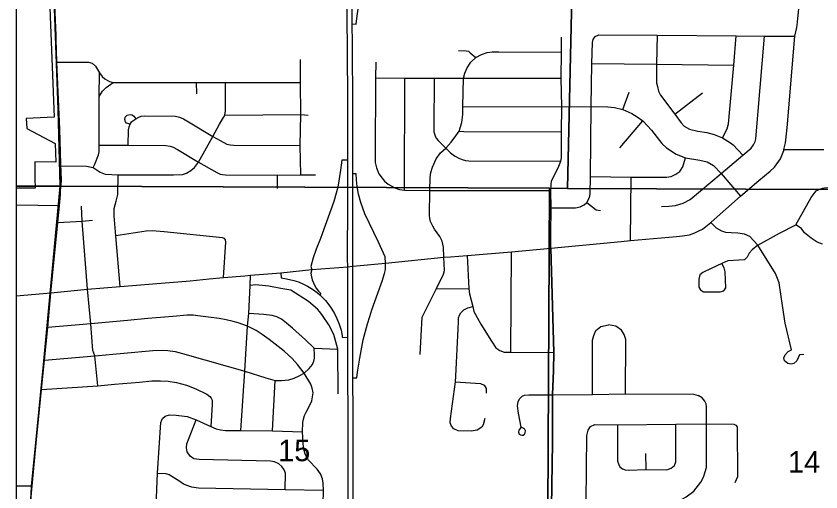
# Model space of a CAD drawing. Extents: x -38.1 to 35.9, y -2.7 to 28.5.
# Drawn here: x 8.115 to 9.678, y 15.282 to 16.206 of the extents above; entities that cross this region are included whole.
import ezdxf

# ---------------------------------------------------------------- set-up
doc = ezdxf.new("R2010")
doc.units = 0
for name, color, linetype in [('GM_X_City_Street', 7, 'Continuous'), ('GM_X_City_Street_Text', 7, 'Continuous'), ('GM_X_Corporation', 7, 'Continuous'), ('GM_X_Corporation_Text', 7, 'Continuous'), ('GM_X_Major_River', 7, 'Continuous'), ('GM_X_Minor_River', 7, 'Continuous'), ('GM_X_Rail_Line_Text', 7, 'Continuous'), ('GM_X_US_Route', 7, 'Continuous')]:
    doc.layers.add(name, color=color, linetype=linetype)

msp = doc.modelspace()

# ---------------------------------------------------------------- linework, layer by layer
at = {"layer": 'GM_X_City_Street'}
for p, q in [((8.8687, 15.8678), (8.8694, 16.0858)), ((8.4654, 16.055), (8.4653, 16.077)), ((9.2932, 16.0244), (9.3049, 16.0583)), ((9.3937, 16.0157), (9.4475, 16.0568)), ((9.2869, 15.9502), (9.3317, 16.0024)), ((9.6058, 15.947), (9.6831, 15.9473)), ((8.6221, 15.8716), (8.6225, 15.897)), ((9.3075, 15.7701), (9.3088, 15.8935)), ((8.1146, 15.8394), (8.1991, 15.8385)), ((9.153, 15.7552), (9.1532, 15.7832)), ((9.153, 15.7552), (9.2899, 15.7684)), ((9.0756, 15.5533), (9.0768, 15.7482)), ((8.9311, 15.6771), (8.9937, 15.6767)), ((8.6936, 15.5616), (8.7394, 15.5592)), ((8.2731, 15.4881), (8.2681, 15.5401)), ((8.6127, 15.4007), (8.618, 15.4988)), ((9.3383, 15.3258), (9.3378, 15.3567)), ((8.1146, 15.2942), (8.1449, 15.2942))]:
    msp.add_line(p, q, dxfattribs=at)
for points in [[(9.6318, 16.194), (9.6477, 16.3507), (9.6404, 16.3717), (9.6476, 16.4723), (9.6557, 16.5731), (9.6614, 16.6273), (9.6602, 16.6447), (9.6546, 16.6676), (9.6322, 16.744), (9.6013, 16.8489), (9.5885, 16.8705), (9.5494, 16.9278), (9.5194, 16.9778), (9.4899, 17.0395), (9.4492, 17.1302), (9.4087, 17.2248), (9.3808, 17.2922), (9.3578, 17.3731), (9.3429, 17.4462)], [(9.5876, 15.9128), (9.5988, 15.9287), (9.6054, 15.9452), (9.6058, 15.947), (9.6089, 15.9597), (9.6121, 15.9891), (9.6172, 16.0506), (9.6232, 16.1212), (9.6272, 16.1669), (9.6308, 16.1841), (9.6318, 16.194)], [(9.1532, 15.7832), (9.1536, 15.8337), (9.1531, 15.8674), (9.1536, 15.8794), (9.1547, 15.8857), (9.1606, 15.899), (9.1673, 15.9117), (9.1723, 15.9242), (9.1736, 15.9311), (9.1738, 15.9812), (9.1742, 16.0297), (9.1734, 16.0855), (9.1741, 16.1361), (9.1739, 16.1653)], [(9.1536, 15.8337), (9.2013, 15.8335), (9.2101, 15.8358), (9.2176, 15.8397), (9.2229, 15.8443), (9.2282, 15.8542), (9.2295, 15.8606), (9.2302, 15.8945), (9.2312, 16.0303), (9.2325, 16.1143), (9.2338, 16.1547), (9.2352, 16.1603), (9.2393, 16.1663), (9.2462, 16.1699), (9.3598, 16.1691), (9.5133, 16.1679), (9.5683, 16.1673), (9.6272, 16.1669)], [(9.3598, 16.1691), (9.3585, 16.1128), (9.3585, 16.0764), (9.3601, 16.0693), (9.3624, 16.0602), (9.3659, 16.0527), (9.3937, 16.0157), (9.4063, 15.9989), (9.4122, 15.9924), (9.4227, 15.9863), (9.4384, 15.9829), (9.456, 15.9801), (9.4702, 15.9764), (9.4863, 15.9698), (9.5023, 15.9597), (9.5075, 15.9559), (9.5258, 15.9362)], [(9.3679, 15.8364), (9.3823, 15.8369), (9.3953, 15.8382), (9.4103, 15.8426), (9.4239, 15.85), (9.4842, 15.9002), (9.5258, 15.9362), (9.5424, 15.9499), (9.5468, 15.956), (9.5496, 15.9626), (9.551, 15.968), (9.5683, 16.1673)], [(9.4863, 15.9698), (9.4957, 15.987), (9.4984, 15.9972), (9.5086, 16.1111), (9.5133, 16.1679)], [(8.8993, 15.5493), (8.9033, 15.6217), (8.9068, 15.6296), (8.9311, 15.6771), (8.9447, 15.705), (8.9468, 15.7123), (8.9456, 15.7378), (8.9445, 15.7577), (8.942, 15.769), (8.9375, 15.7781), (8.9275, 15.7921), (8.9238, 15.798), (8.9195, 15.8073), (8.9182, 15.8133), (8.9176, 15.8194), (8.9183, 15.8677), (8.919, 15.8929), (8.9201, 15.9026), (8.9233, 15.9127), (8.9306, 15.9291), (8.9391, 15.9403), (8.9494, 15.9498), (8.9598, 15.961), (8.9688, 15.9736), (8.9752, 15.9829), (8.9804, 15.9997), (8.9823, 16.0147), (8.9822, 16.0303), (8.9836, 16.0854), (8.9861, 16.0951), (8.9905, 16.1054), (8.9979, 16.1163), (9.0073, 16.1257), (9.0184, 16.1316), (9.0292, 16.1351), (9.039, 16.1367), (9.052, 16.1366), (9.1741, 16.1361)], [(8.9735, 16.139), (8.9884, 16.1386), (8.993, 16.1377), (8.9967, 16.135), (9.0073, 16.1257)], [(8.1939, 16.1168), (8.2469, 16.1168), (8.2552, 16.1165), (8.2622, 16.1144), (8.2691, 16.1091), (8.2765, 16.0958), (8.2819, 16.0889), (8.2872, 16.084), (8.296, 16.0793), (8.3032, 16.077), (8.3141, 16.077), (8.4653, 16.077), (8.5215, 16.077), (8.6672, 16.0773)], [(8.6673, 15.8982), (8.6665, 15.9547), (8.6673, 16.0153), (8.6672, 16.0773), (8.6671, 16.1219)], [(8.813, 16.1163), (8.8127, 16.0859), (8.812, 15.9324), (8.812, 15.9219), (8.8143, 15.9113), (8.8191, 15.8999), (8.83, 15.8855), (8.8373, 15.8796), (8.8503, 15.8726), (8.8589, 15.8697), (8.8687, 15.8678), (8.9183, 15.8677), (9.1531, 15.8674)], [(9.2325, 16.1143), (9.3585, 16.1128), (9.5086, 16.1111)], [(8.2643, 15.9124), (8.2678, 15.9185), (8.2746, 15.9369), (8.276, 15.9428), (8.2759, 15.9557), (8.2761, 16.0502), (8.2765, 16.0958)], [(8.8127, 16.0859), (8.8694, 16.0858), (8.9264, 16.0854), (8.9836, 16.0854), (9.1734, 16.0855)], [(8.9264, 16.0854), (8.9258, 15.9885), (8.9259, 15.9811), (8.9285, 15.9734), (8.9307, 15.9688), (8.9344, 15.9643), (8.9494, 15.9498), (8.9585, 15.9403), (8.9661, 15.9347), (8.9742, 15.9304), (8.9807, 15.9275), (8.9873, 15.9256), (8.9938, 15.9248), (9.1723, 15.9242)], [(8.2761, 16.0502), (8.2827, 16.0604), (8.2897, 16.0674), (8.3032, 16.077)], [(8.469, 15.9226), (8.4967, 15.9723), (8.5097, 15.9963), (8.5177, 16.0091), (8.5202, 16.0137), (8.5214, 16.0219), (8.5215, 16.077)], [(8.9822, 16.0303), (9.1742, 16.0297), (9.2312, 16.0303), (9.2636, 16.0296), (9.2766, 16.0283), (9.2932, 16.0244), (9.3103, 16.0172), (9.3207, 16.0108), (9.3317, 16.0024), (9.3489, 15.9848), (9.3687, 15.9584), (9.3774, 15.9502), (9.3964, 15.9381), (9.4147, 15.9309), (9.4426, 15.9265), (9.4565, 15.923), (9.4691, 15.9158), (9.4842, 15.9002), (9.5216, 15.8564)], [(8.3363, 15.9961), (8.3291, 15.9985), (8.3271, 16.001), (8.3261, 16.005), (8.3266, 16.01), (8.3303, 16.0137), (8.3361, 16.0153), (8.3399, 16.0141), (8.3433, 16.012), (8.347, 16.0068)], [(8.3325, 15.9553), (8.3328, 15.9855), (8.3341, 15.9912), (8.3363, 15.9961), (8.3397, 16.0015), (8.347, 16.0068), (8.3528, 16.01), (8.3574, 16.0117), (8.3649, 16.0122), (8.4243, 16.0115), (8.432, 16.0096), (8.4396, 16.0064), (8.4524, 15.9991), (8.4967, 15.9723), (8.5108, 15.9644), (8.5241, 15.9574), (8.5302, 15.956), (8.5377, 15.9556), (8.6665, 15.9547)], [(8.5202, 16.0137), (8.6673, 16.0153), (8.6817, 16.0139)], [(8.9752, 15.9829), (8.9843, 15.9818), (9.1738, 15.9812)], [(8.2759, 15.9557), (8.3325, 15.9553), (8.4055, 15.9549), (8.4136, 15.9536), (8.4196, 15.9513), (8.4279, 15.9473), (8.469, 15.9226), (8.5046, 15.9021), (8.5107, 15.8994), (8.5158, 15.8985), (8.5215, 15.8979), (8.6225, 15.897), (8.6673, 15.8982), (8.696, 15.8979)], [(9.2302, 15.8945), (9.3088, 15.8935), (9.3777, 15.8931), (9.3871, 15.8945), (9.3958, 15.8989), (9.4034, 15.9043), (9.4092, 15.9131), (9.4147, 15.9309)], [(8.2017, 15.9152), (8.2515, 15.9145), (8.2643, 15.9124), (8.2781, 15.9032), (8.2877, 15.8991), (8.3126, 15.8978), (8.4206, 15.8982), (8.4381, 15.8983), (8.4458, 15.901), (8.4539, 15.9066), (8.461, 15.9124), (8.469, 15.9226)], [(9.2899, 15.7684), (9.3075, 15.7701), (9.397, 15.778), (9.409, 15.7792), (9.4223, 15.7815), (9.4326, 15.7851), (9.4408, 15.7889), (9.4478, 15.7927), (9.4638, 15.8054), (9.4647, 15.8061), (9.5216, 15.8564), (9.5571, 15.887), (9.5791, 15.9052), (9.5876, 15.9128)], [(8.3168, 15.6812), (8.3085, 15.7797), (8.3051, 15.8182), (8.3049, 15.8324), (8.3087, 15.847), (8.3125, 15.8595), (8.3126, 15.8978)], [(9.5552, 15.7611), (9.5972, 15.7849), (9.6291, 15.8009), (9.6587, 15.8537), (9.6684, 15.8667), (9.6805, 15.8722), (9.6879, 15.8736), (9.723, 15.8722), (9.7317, 15.869)], [(8.2536, 15.676), (8.2432, 15.8082), (8.2415, 15.8369)], [(9.2229, 15.8443), (9.2414, 15.8297), (9.2495, 15.8285)], [(8.196, 15.8054), (8.2432, 15.8082), (8.2629, 15.8098)], [(9.6445, 15.5489), (9.636, 15.5482), (9.6306, 15.5368), (9.6253, 15.5314), (9.6199, 15.5302), (9.6136, 15.5313), (9.6066, 15.537), (9.6054, 15.5423), (9.608, 15.5485), (9.6138, 15.5552), (9.6204, 15.558), (9.608, 15.6099), (9.6032, 15.6443), (9.5964, 15.688), (9.5934, 15.6966), (9.5891, 15.7063), (9.5552, 15.7611), (9.5396, 15.7781), (9.5294, 15.7826), (9.5161, 15.7849), (9.5035, 15.7855), (9.4932, 15.7862), (9.4852, 15.7884), (9.4746, 15.7941), (9.4638, 15.8054)], [(8.5175, 15.6983), (8.5218, 15.7672), (8.5214, 15.7715), (8.5195, 15.7742), (8.5155, 15.7758), (8.4019, 15.787), (8.3788, 15.7893), (8.3673, 15.7886), (8.3085, 15.7797)], [(9.6808, 15.7634), (9.6702, 15.7671), (9.6585, 15.775), (9.646, 15.7856), (9.6396, 15.7935), (9.6291, 15.8009)], [(9.158, 15.518), (9.1591, 15.5529), (9.153, 15.7552)], [(9.5552, 15.7611), (9.5439, 15.7525), (9.5381, 15.7459), (9.5342, 15.7378), (9.5292, 15.7331), (9.4966, 15.7308), (9.4853, 15.7258), (9.4644, 15.7163), (9.4482, 15.7085), (9.4425, 15.7037), (9.4407, 15.6951), (9.4408, 15.6799), (9.4437, 15.6745), (9.4496, 15.671), (9.4818, 15.6706), (9.4888, 15.673), (9.4927, 15.6788), (9.4919, 15.7098), (9.4896, 15.7172), (9.4853, 15.7258)], [(8.9907, 15.7416), (8.9937, 15.6767), (8.9952, 15.6668), (9.0013, 15.6422), (9.0038, 15.6323), (9.017, 15.608), (9.038, 15.5749), (9.0461, 15.5618), (9.0539, 15.5569), (9.0626, 15.5539), (9.0756, 15.5533), (9.1591, 15.5529)], [(8.5514, 15.4014), (8.5591, 15.5164), (8.5642, 15.6041), (8.5663, 15.6288), (8.5694, 15.6832), (8.57, 15.7031)], [(8.7402, 15.4726), (8.7394, 15.5592), (8.7319, 15.5876), (8.7219, 15.6069), (8.7097, 15.6249), (8.7047, 15.6319), (8.6997, 15.6369), (8.6826, 15.6517), (8.6481, 15.6738), (8.6285, 15.6775), (8.6055, 15.6816), (8.5794, 15.6843), (8.5694, 15.6832)], [(8.2681, 15.5401), (8.2675, 15.5463), (8.2636, 15.5571), (8.2597, 15.6085), (8.2536, 15.676)], [(9.0251, 15.4246), (9.0219, 15.4125), (9.0189, 15.4079), (9.0102, 15.4021), (8.9984, 15.4), (8.9729, 15.4011), (8.9646, 15.4049), (8.9602, 15.4102), (8.9579, 15.4164), (8.9581, 15.4246), (8.9678, 15.4958), (8.9683, 15.5071), (8.9733, 15.5992), (8.9736, 15.6129), (8.9741, 15.6203), (8.9756, 15.6252), (8.9784, 15.63), (8.9844, 15.6359), (8.9919, 15.64), (9.0013, 15.6422)], [(8.1698, 15.5383), (8.2675, 15.5463), (8.3805, 15.557), (8.3987, 15.5576), (8.4091, 15.5567), (8.4236, 15.5546), (8.4379, 15.5511), (8.5246, 15.5262), (8.5591, 15.5164), (8.5998, 15.5041), (8.618, 15.4988), (8.6302, 15.4987), (8.6442, 15.5001), (8.6547, 15.5033), (8.6642, 15.5076), (8.6741, 15.513), (8.684, 15.5216), (8.69, 15.5295), (8.6928, 15.536), (8.694, 15.5417), (8.6942, 15.5482), (8.6936, 15.5616), (8.6768, 15.5773), (8.6517, 15.5999), (8.6398, 15.6099), (8.6302, 15.6176), (8.6208, 15.6219), (8.6118, 15.6249), (8.5956, 15.627), (8.5663, 15.6288)], [(8.7102, 15.2312), (8.7113, 15.2857), (8.7111, 15.2991), (8.7098, 15.3076), (8.7056, 15.3173), (8.6993, 15.3264), (8.6819, 15.3447), (8.6757, 15.3554), (8.6727, 15.368), (8.6711, 15.3989), (8.6717, 15.4172), (8.6727, 15.4238), (8.6746, 15.4307), (8.6777, 15.4372), (8.6852, 15.4506), (8.6887, 15.4591), (8.6905, 15.4672), (8.6914, 15.4749), (8.6899, 15.484), (8.6868, 15.4913), (8.6741, 15.513), (8.6612, 15.5294), (8.6505, 15.5416), (8.6354, 15.5557), (8.6059, 15.5785), (8.5928, 15.5882), (8.581, 15.5956), (8.5642, 15.6041), (8.546, 15.6104), (8.5364, 15.6131), (8.5228, 15.6166), (8.5089, 15.6187), (8.4675, 15.6244), (8.4586, 15.6257), (8.4471, 15.6253), (8.419, 15.6229), (8.3703, 15.619), (8.3312, 15.6148), (8.2597, 15.6085), (8.1765, 15.6016)], [(9.2337, 15.4716), (9.2342, 15.5768), (9.2364, 15.5857), (9.2408, 15.5958), (9.2505, 15.6034), (9.2651, 15.6069)], [(9.2983, 15.4726), (9.2986, 15.5784), (9.2955, 15.5881), (9.2902, 15.5965), (9.2796, 15.604), (9.2651, 15.6069)], [(9.1562, 15.3843), (9.1564, 15.4707), (9.158, 15.518)], [(8.164, 15.481), (8.2731, 15.4881), (8.3059, 15.4913), (8.3544, 15.4954), (8.3781, 15.4982), (8.3951, 15.4982), (8.4102, 15.4973), (8.4264, 15.4946), (8.4454, 15.4894), (8.4639, 15.4825), (8.4848, 15.472), (8.4907, 15.4673), (8.4932, 15.4642), (8.4951, 15.4603), (8.4954, 15.4517), (8.4931, 15.4095)], [(8.9678, 15.4958), (9.0164, 15.493), (9.0236, 15.4896), (9.0274, 15.483), (9.0276, 15.4742)], [(9.0957, 15.4081), (9.0909, 15.4019), (9.0905, 15.3983), (9.0919, 15.3947), (9.0943, 15.393), (9.0969, 15.3927), (9.0993, 15.3927), (9.102, 15.3944), (9.1034, 15.3973), (9.1039, 15.4007), (9.102, 15.4045), (9.0957, 15.4081), (9.0902, 15.4354), (9.0885, 15.4496), (9.0895, 15.4577), (9.0926, 15.4637), (9.0974, 15.4683), (9.1022, 15.47), (9.1104, 15.4709), (9.1564, 15.4707)], [(9.1541, 15.2534), (9.1735, 15.254), (9.1838, 15.2561), (9.1964, 15.26), (9.2043, 15.2616), (9.2217, 15.2622), (9.3768, 15.2609), (9.3879, 15.2618), (9.3968, 15.2636), (9.4066, 15.2674), (9.416, 15.273), (9.4311, 15.2838), (9.4447, 15.3013), (9.4494, 15.311), (9.453, 15.3212), (9.4554, 15.33), (9.4555, 15.4144), (9.4554, 15.4474), (9.455, 15.4534), (9.4521, 15.4586), (9.4468, 15.4649), (9.4392, 15.4696)], [(9.1564, 15.4707), (9.2337, 15.4716), (9.2983, 15.4726), (9.43, 15.4721), (9.4392, 15.4696)], [(8.3954, 15.4168), (8.399, 15.4247), (8.4044, 15.4292), (8.4126, 15.4317), (8.4252, 15.4313), (8.4466, 15.4284), (8.4642, 15.4223), (8.4931, 15.4095), (8.503, 15.405), (8.5115, 15.4028), (8.5215, 15.4017), (8.5514, 15.4014), (8.6127, 15.4007), (8.6711, 15.3989)], [(8.3812, 15.129), (8.3895, 15.3186), (8.3954, 15.4168)], [(8.6372, 15.2868), (8.6375, 15.3184), (8.6355, 15.3251), (8.6308, 15.3316), (8.6248, 15.3368), (8.6165, 15.3408), (8.6085, 15.342), (8.47, 15.345), (8.4596, 15.3468), (8.4525, 15.352), (8.4471, 15.3602), (8.4453, 15.3677), (8.4461, 15.3755), (8.4642, 15.4223)], [(9.221, 15.1973), (9.2217, 15.2622), (9.2233, 15.3916), (9.2256, 15.4022), (9.23, 15.4094), (9.2384, 15.4133)], [(9.2384, 15.4133), (9.2825, 15.4128), (9.3959, 15.4139), (9.4555, 15.4144), (9.5082, 15.4139)], [(9.2825, 15.4128), (9.2828, 15.3422), (9.2845, 15.3366), (9.287, 15.3309), (9.2924, 15.3269), (9.2975, 15.3252), (9.3038, 15.3247), (9.3383, 15.3258), (9.3783, 15.3252), (9.3871, 15.3281), (9.393, 15.3337), (9.3959, 15.3408), (9.3959, 15.4139)], [(9.5082, 15.4139), (9.5126, 15.4117), (9.5149, 15.4086), (9.5157, 15.3117), (9.5104, 15.3002)], [(9.1532, 15.0542), (9.154, 15.1979), (9.1541, 15.2534), (9.1562, 15.3781), (9.1562, 15.3843)], [(8.3895, 15.3186), (8.405, 15.3178), (8.4121, 15.3161), (8.4323, 15.3033), (8.4397, 15.2982), (8.4477, 15.2945), (8.4555, 15.2922), (8.4686, 15.2902), (8.6372, 15.2868), (8.7113, 15.2857)]]:
    msp.add_lwpolyline(points, dxfattribs=at)
at = {"layer": 'GM_X_City_Street_Text'}
for points in [[(8.1924, 16.1683), (8.1862, 16.3191), (8.1838, 16.379), (8.18, 16.4801), (8.1761, 16.6146), (8.17, 16.7523), (8.1676, 16.8777), (8.1677, 16.8817)], [(8.2016, 15.9183), (8.1998, 15.9866), (8.1939, 16.1168), (8.1927, 16.1613), (8.1924, 16.1683)], [(8.2011, 15.8679), (8.2017, 15.9152), (8.2016, 15.9183)], [(8.182, 15.6689), (8.196, 15.8054), (8.1991, 15.8385), (8.201, 15.8598), (8.2011, 15.8679)], [(8.1334, 14.783), (8.1334, 14.787), (8.1336, 14.9983), (8.1361, 15.0673), (8.1365, 15.1338), (8.1382, 15.2043), (8.1449, 15.2942), (8.1506, 15.3447), (8.164, 15.481), (8.1698, 15.5383), (8.1765, 15.6016), (8.182, 15.6689)]]:
    msp.add_lwpolyline(points, dxfattribs=at)
at = {"layer": 'GM_X_Corporation'}
msp.add_lwpolyline([(8.1169, 12.9308), (8.1202, 13.4509), (8.1267, 14.3761), (8.1272, 14.5808), (8.1295, 14.9033), (8.1448, 15.2944), (8.1561, 15.4105), (8.2031, 15.8872), (8.1758, 16.5559), (8.1657, 16.8852), (8.1819, 17.1843), (8.2212, 17.8697), (8.2224, 17.8749)], dxfattribs=at)
at = {"layer": 'GM_X_Corporation_Text'}
for points in [[(8.7594, 15.2455), (8.7597, 15.3293), (8.7594, 15.4349), (8.759, 15.5044), (8.759, 15.5824), (8.7589, 15.6629), (8.7589, 15.712), (8.7588, 15.7195), (8.7585, 15.7349), (8.7589, 15.8455), (8.759, 15.8997), (8.7587, 15.9265), (8.759, 16.0287), (8.758, 16.1522), (8.7577, 16.1907), (8.7582, 16.2702), (8.7587, 16.3653), (8.7587, 16.3728), (8.7586, 16.3972), (8.7582, 16.4663), (8.7584, 16.4935)], [(8.7691, 15.245), (8.7694, 15.3287), (8.7691, 15.4343), (8.7688, 15.5039), (8.7688, 15.5819), (8.7686, 15.6631), (8.7686, 15.7123), (8.7685, 15.7204), (8.7683, 15.7352), (8.7686, 15.8457), (8.7687, 15.9), (8.7684, 15.9268), (8.7688, 16.029), (8.7678, 16.1525), (8.7675, 16.191), (8.7679, 16.2705)]]:
    msp.add_lwpolyline(points, dxfattribs=at)
at = {"layer": 'GM_X_Major_River'}
for points in [[(8.9583, 15.7389), (8.9907, 15.7416), (9.0768, 15.7482), (9.153, 15.7552)], [(9.153, 15.7552), (9.1591, 15.5529), (9.158, 15.518)], [(8.5591, 15.7021), (8.57, 15.7031), (8.6285, 15.7076), (8.689, 15.7143), (8.7588, 15.7195), (8.7636, 15.7199), (8.7685, 15.7204), (8.8322, 15.7267), (8.9456, 15.7378), (8.9583, 15.7389)], [(8.3803, 15.6864), (8.4527, 15.6923), (8.4896, 15.6957)], [(8.4896, 15.6957), (8.5175, 15.6983), (8.5591, 15.7021)], [(8.1146, 15.6629), (8.182, 15.6689), (8.2536, 15.676), (8.3168, 15.6812), (8.3803, 15.6864)], [(9.158, 15.518), (9.1564, 15.4707), (9.1562, 15.3843)], [(9.1562, 15.3843), (9.1562, 15.3781), (9.1541, 15.2534), (9.154, 15.1979), (9.1532, 15.0542)]]:
    msp.add_lwpolyline(points, dxfattribs=at)
at = {"layer": 'GM_X_Rail_Line_Text'}
for points in [[(8.7675, 16.191), (8.7749, 16.1906), (8.7779, 16.2116), (8.7846, 16.2547), (8.7892, 16.2756), (8.7929, 16.2904)], [(8.7587, 15.9265), (8.7471, 15.9262), (8.7448, 15.9072), (8.7393, 15.8739), (8.7318, 15.8464), (8.7091, 15.7836), (8.7055, 15.7746)], [(8.8322, 15.7267), (8.8313, 15.7385), (8.8184, 15.7669), (8.7921, 15.8224), (8.7842, 15.8439), (8.7796, 15.8605), (8.7771, 15.8753), (8.7758, 15.888), (8.7752, 15.9), (8.7687, 15.9)], [(8.7055, 15.7746), (8.6972, 15.7536), (8.6918, 15.7367), (8.6871, 15.7198), (8.689, 15.7143)], [(8.8014, 15.6231), (8.8054, 15.6356), (8.8171, 15.668), (8.8254, 15.6916), (8.8302, 15.7065), (8.8322, 15.714), (8.8322, 15.7267)], [(8.6285, 15.7076), (8.6291, 15.6978), (8.6399, 15.6962), (8.6538, 15.693), (8.6629, 15.6899), (8.6727, 15.6858), (8.6803, 15.6818), (8.69, 15.6759), (8.699, 15.6692), (8.7042, 15.6647), (8.7069, 15.6623), (8.7153, 15.6537), (8.7222, 15.6453), (8.7278, 15.6372), (8.7329, 15.6287), (8.7377, 15.6188), (8.742, 15.6078), (8.7457, 15.5966), (8.7479, 15.586), (8.748, 15.583), (8.759, 15.5824)], [(8.689, 15.7143), (8.6868, 15.707), (8.6882, 15.6999), (8.6897, 15.6943), (8.692, 15.6882), (8.6942, 15.6835), (8.6975, 15.678), (8.7018, 15.6723), (8.7066, 15.6675), (8.7042, 15.6647)], [(8.7688, 15.5039), (8.7764, 15.5041), (8.7779, 15.5145), (8.782, 15.542), (8.7887, 15.5774), (8.7968, 15.6086), (8.8014, 15.6231)]]:
    msp.add_lwpolyline(points, dxfattribs=at)
at = {"layer": 'GM_X_US_Route'}
for points in [[(8.1146, 17.8763), (8.1146, 12.9308), (14.9146, 12.9308)], [(8.1146, 17.8763), (8.1146, 12.9308)], [(10.0492, 15.8683), (9.1857, 15.8712), (9.2082, 16.8722)], [(8.1748, 16.3775), (8.1807, 16.2052), (8.1885, 16.0096), (8.1344, 16.0075), (8.1352, 15.9879), (8.1905, 15.9585), (8.1916, 15.9225), (8.1509, 15.9229), (8.1513, 15.8895), (8.1514, 15.8729), (8.1515, 15.8719), (8.141, 15.8719), (8.14, 15.872), (8.128, 15.872), (8.1274, 15.872), (8.1146, 15.872), (8.1146, 13.916)]]:
    msp.add_lwpolyline(points, dxfattribs=at)
for points in [[(8.1146, 16.8798), (8.1146, 15.8757), (8.2, 15.8756), (8.1963, 16.0249), (8.1654, 16.8799)], [(8.1654, 16.8799), (9.2082, 16.8722), (9.1857, 15.8712), (9.1505, 15.8719), (8.2, 15.8756), (8.1963, 16.0249)], [(8.1146, 15.8757), (8.1146, 14.9056), (8.1296, 14.9066), (8.1379, 15.2106), (8.2, 15.8756)], [(8.2, 15.8756), (9.1505, 15.8719), (9.1455, 14.871), (8.1296, 14.9066), (8.1379, 15.2106)], [(9.1505, 15.8719), (9.1857, 15.8712), (10.0492, 15.8683), (10.0548, 15.8626), (10.0625, 15.8533), (10.0673, 15.8468), (10.0758, 15.8357), (10.0814, 15.8287), (10.0851, 15.8249), (10.0967, 15.816), (10.1026, 15.8105), (10.1237, 15.7848), (10.1304, 15.7756), (10.1459, 15.7537), (10.1489, 14.8625), (9.1455, 14.871)]]:
    msp.add_lwpolyline(points, close=True, dxfattribs=at)

# ---------------------------------------------------------------- texts
at = {"layer": 'GM_X_Minor_River'}
for s, p in [('15', (8.6237, 15.3419)), ('14', (9.6137, 15.3196))]:
    msp.add_text(s, height=0.04186, rotation=0, dxfattribs=at).set_placement(p)

doc.saveas('drawing.dxf')
